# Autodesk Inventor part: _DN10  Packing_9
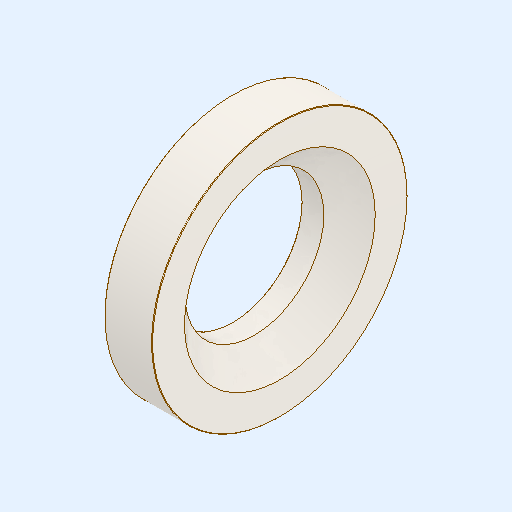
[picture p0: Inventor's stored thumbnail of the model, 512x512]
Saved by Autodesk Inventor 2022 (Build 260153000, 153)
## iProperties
Created: 2021-12
Part Number: _DN10  Packing_9
Material: Generico
Document SubType Name: Modeling
Designer: admin
Density: 1 g/cm^3
Appearance: Default
Author: admin
Revision Number: NONE
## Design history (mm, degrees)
feature "_DN10  Packing"
node "Solido1"
